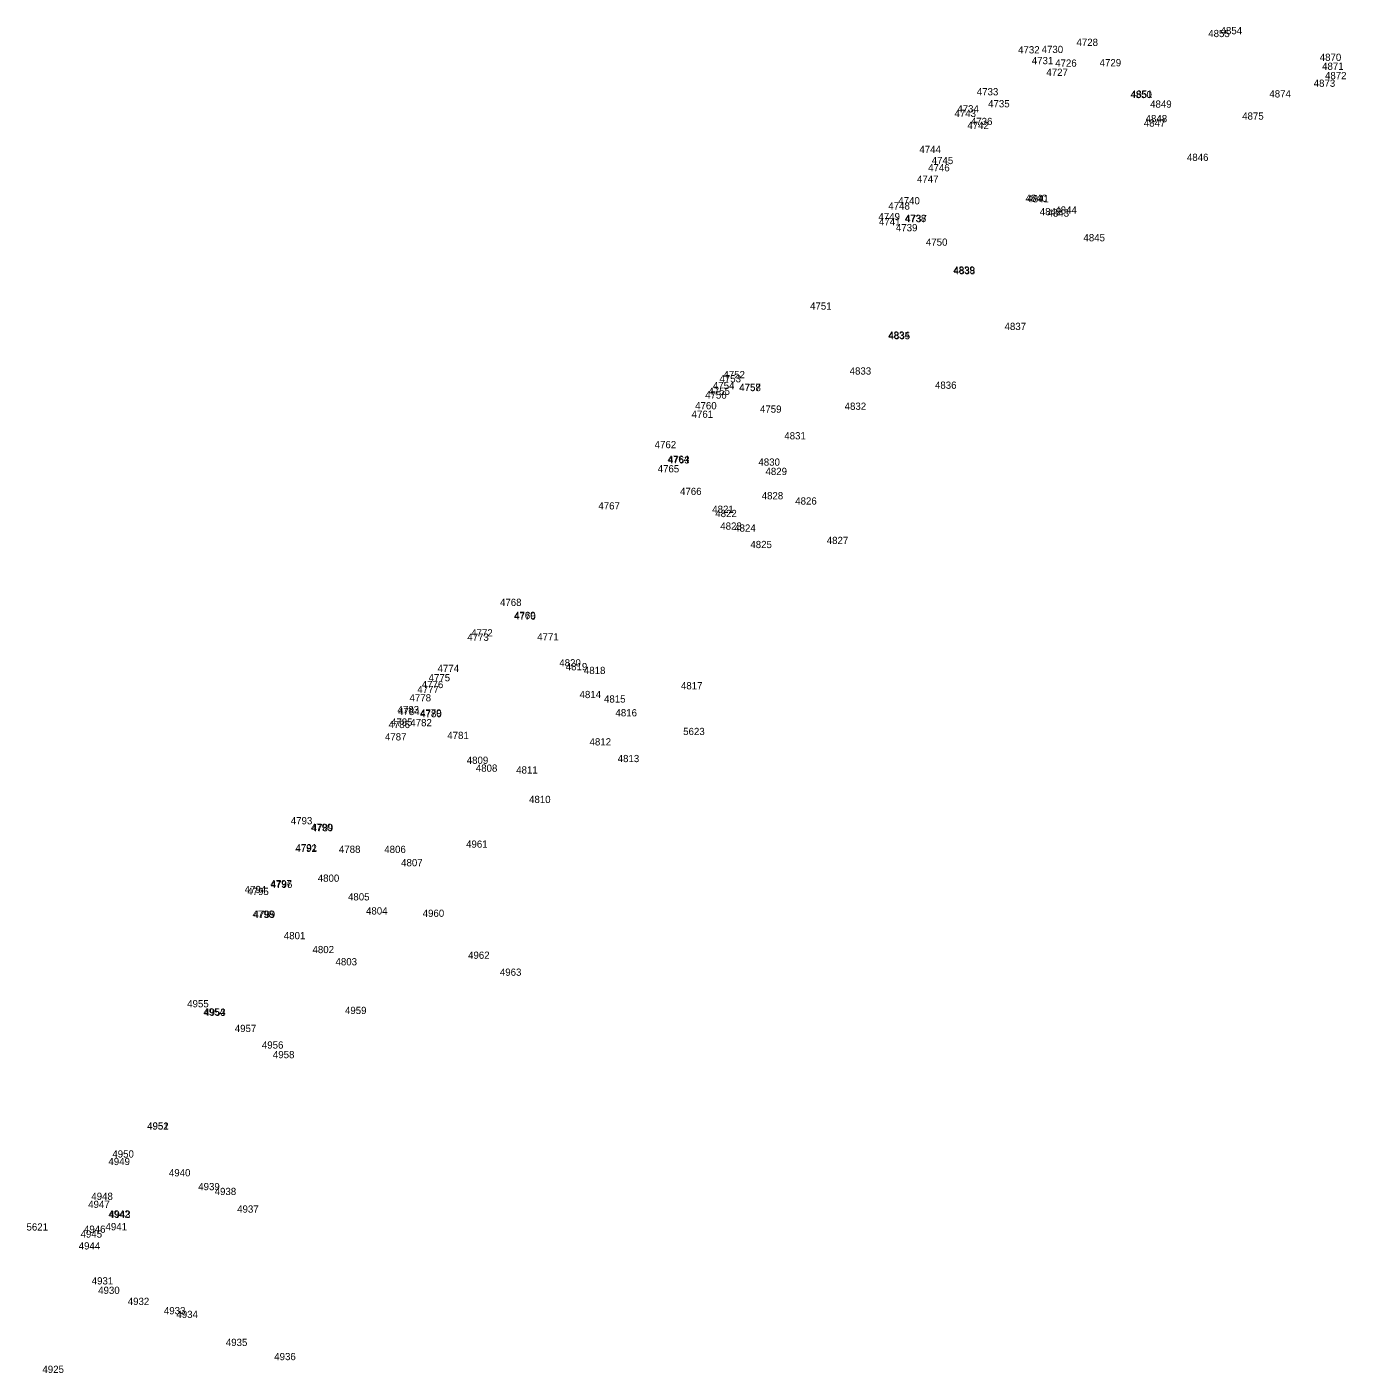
# Model space of a CAD drawing. Extents: x -740053 to -737517, y -1033516 to -1032488.
# Drawn here: x -738891.2 to -738790.9, y -1032757.6 to -1032655.2 of the extents above; entities that cross this region are included whole.
import ezdxf

# ---------------------------------------------------------------- set-up
doc = ezdxf.new("R2010")
doc.units = 0
doc.layers.add('bod-cislo', color=7, linetype='Continuous')

msp = doc.modelspace()

# ---------------------------------------------------------------- texts
at = {"layer": 'bod-cislo'}
for s, p in [('4855', (-738801.34, -1032656.02)), ('4854', (-738800.4, -1032655.8)), ('4728', (-738811.36, -1032656.69)), ('4732', (-738815.8, -1032657.26)), ('4731', (-738814.76, -1032658.08)), ('4730', (-738814.01, -1032657.23)), ('4870', (-738792.86, -1032657.83)), ('4727', (-738813.65, -1032658.97)), ('4726', (-738812.98, -1032658.27)), ('4729', (-738809.6, -1032658.24)), ('4871', (-738792.68, -1032658.51)), ('4873', (-738793.32, -1032659.8)), ('4872', (-738792.46, -1032659.22)), ('4733', (-738818.94, -1032660.45)), ('4850', (-738807.26, -1032660.66)), ('4851', (-738807.22, -1032660.63)), ('4874', (-738796.69, -1032660.61)), ('4743', (-738820.64, -1032662.1)), ('4734', (-738820.42, -1032661.75)), ('4735', (-738818.08, -1032661.36)), ('4849', (-738805.76, -1032661.39)), ('4742', (-738819.66, -1032663.01)), ('4736', (-738819.39, -1032662.71)), ('4847', (-738806.24, -1032662.83)), ('4848', (-738806.1, -1032662.49)), ('4875', (-738798.76, -1032662.3)), ('4744', (-738823.31, -1032664.84)), ('4746', (-738822.64, -1032666.23)), ('4745', (-738822.37, -1032665.68)), ('4846', (-738802.96, -1032665.44)), ('4747', (-738823.49, -1032667.1)), ('4748', (-738825.67, -1032669.14)), ('4740', (-738824.91, -1032668.74)), ('4840', (-738815.23, -1032668.55)), ('4841', (-738815.1, -1032668.59)), ('4749', (-738826.42, -1032669.95)), ('4741', (-738826.38, -1032670.34)), ('4738', (-738824.42, -1032670.08)), ('4737', (-738824.38, -1032670.1)), ('4842', (-738814.15, -1032669.57)), ('4843', (-738813.56, -1032669.68)), ('4844', (-738812.97, -1032669.45)), ('4739', (-738825.09, -1032670.79)), ('4750', (-738822.81, -1032671.89)), ('4845', (-738810.83, -1032671.55)), ('4839', (-738820.73, -1032674.01)), ('4838', (-738820.7, -1032674.06)), ('4751', (-738831.62, -1032676.75)), ('4837', (-738816.83, -1032678.3)), ('4834', (-738825.68, -1032678.96)), ('4835', (-738825.65, -1032679)), ('4753', (-738838.51, -1032682.28)), ('4752', (-738838.21, -1032681.97)), ('4833', (-738828.61, -1032681.69)), ('4756', (-738839.6, -1032683.52)), ('4755', (-738839.35, -1032683.23)), ('4754', (-738839.01, -1032682.8)), ('4757', (-738837.01, -1032682.93)), ('4758', (-738837, -1032682.95)), ('4836', (-738822.12, -1032682.77)), ('4760', (-738840.36, -1032684.33)), ('4759', (-738835.43, -1032684.59)), ('4832', (-738828.99, -1032684.37)), ('4761', (-738840.63, -1032684.98)), ('4831', (-738833.58, -1032686.62)), ('4762', (-738843.44, -1032687.29)), ('4764', (-738842.46, -1032688.4)), ('4763', (-738842.42, -1032688.45)), ('4830', (-738835.55, -1032688.62)), ('4765', (-738843.21, -1032689.13)), ('4829', (-738835.01, -1032689.33)), ('4766', (-738841.51, -1032690.85)), ('4828', (-738835.3, -1032691.18)), ('4826', (-738832.75, -1032691.58)), ('4767', (-738847.72, -1032691.95)), ('4821', (-738839.06, -1032692.21)), ('4822', (-738838.83, -1032692.53)), ('4823', (-738838.45, -1032693.49)), ('4824', (-738837.39, -1032693.64)), ('4825', (-738836.16, -1032694.89)), ('4827', (-738830.35, -1032694.58)), ('4768', (-738855.2, -1032699.29)), ('4769', (-738854.13, -1032700.28)), ('4770', (-738854.12, -1032700.34)), ('4773', (-738857.69, -1032701.94)), ('4772', (-738857.39, -1032701.61)), ('4771', (-738852.37, -1032701.91)), ('4820', (-738850.69, -1032703.89)), ('4819', (-738850.2, -1032704.18)), ('4775', (-738860.63, -1032705.02)), ('4774', (-738859.95, -1032704.31)), ('4818', (-738848.82, -1032704.47)), ('4777', (-738861.49, -1032705.92)), ('4776', (-738861.15, -1032705.54)), ('4817', (-738841.44, -1032705.63)), ('4778', (-738862.08, -1032706.55)), ('4814', (-738849.15, -1032706.3)), ('4815', (-738847.29, -1032706.64)), ('4783', (-738862.99, -1032707.45)), ('4784', (-738862.95, -1032707.59)), ('4779', (-738861.28, -1032707.7)), ('4780', (-738861.27, -1032707.76)), ('4816', (-738846.42, -1032707.69)), ('4786', (-738863.68, -1032708.58)), ('4785', (-738863.49, -1032708.4)), ('4782', (-738862.02, -1032708.44)), ('5623', (-738841.27, -1032709.11)), ('4787', (-738863.95, -1032709.52)), ('4781', (-738859.21, -1032709.41)), ('4812', (-738848.39, -1032709.9)), ('4809', (-738857.73, -1032711.3)), ('4813', (-738846.25, -1032711.17)), ('4808', (-738857.04, -1032711.9)), ('4811', (-738853.97, -1032712.04)), ('4810', (-738852.99, -1032714.28)), ('4793', (-738871.11, -1032715.9)), ('4790', (-738869.58, -1032716.4)), ('4789', (-738869.52, -1032716.43)), ('4792', (-738870.77, -1032718)), ('4791', (-738870.74, -1032717.95)), ('4788', (-738867.45, -1032718.07)), ('4806', (-738864, -1032718.08)), ('4961', (-738857.78, -1032717.68)), ('4807', (-738862.72, -1032719.09)), ('4800', (-738869.06, -1032720.27)), ('4794', (-738874.62, -1032721.13)), ('4795', (-738874.42, -1032721.28)), ('4797', (-738872.67, -1032720.69)), ('4796', (-738872.63, -1032720.74)), ('4805', (-738866.76, -1032721.69)), ('4798', (-738874.02, -1032723.01)), ('4799', (-738873.94, -1032723.02)), ('4804', (-738865.39, -1032722.76)), ('4960', (-738861.08, -1032722.94)), ('4801', (-738871.64, -1032724.64)), ('4802', (-738869.46, -1032725.7)), ('4803', (-738867.71, -1032726.63)), ('4962', (-738857.63, -1032726.13)), ('4963', (-738855.21, -1032727.42)), ('4955', (-738878.99, -1032729.82)), ('4954', (-738877.76, -1032730.44)), ('4953', (-738877.7, -1032730.47)), ('4959', (-738866.99, -1032730.33)), ('4957', (-738875.37, -1032731.7)), ('4956', (-738873.31, -1032732.96)), ('4958', (-738872.47, -1032733.69)), ('4952', (-738882.04, -1032739.13)), ('4951', (-738882.03, -1032739.11)), ('4949', (-738884.98, -1032741.82)), ('4950', (-738884.68, -1032741.25)), ('4940', (-738880.38, -1032742.68)), ('4939', (-738878.15, -1032743.73)), ('4938', (-738876.9, -1032744.1)), ('4947', (-738886.52, -1032745.08)), ('4948', (-738886.28, -1032744.47)), ('4942', (-738884.98, -1032745.81)), ('4943', (-738884.93, -1032745.85)), ('4937', (-738875.19, -1032745.44)), ('5621', (-738891.21, -1032746.8)), ('4946', (-738886.84, -1032746.97)), ('4941', (-738885.2, -1032746.78)), ('4945', (-738887.1, -1032747.34)), ('4944', (-738887.24, -1032748.24)), ('4931', (-738886.25, -1032750.9)), ('4930', (-738885.76, -1032751.62)), ('4932', (-738883.51, -1032752.46)), ('4933', (-738880.76, -1032753.17)), ('4934', (-738879.81, -1032753.45)), ('4935', (-738876.05, -1032755.58)), ('4936', (-738872.37, -1032756.66)), ('4925', (-738890, -1032757.63))]:
    msp.add_text(s, height=0.55, dxfattribs=at).set_placement(p)

doc.saveas('drawing.dxf')
